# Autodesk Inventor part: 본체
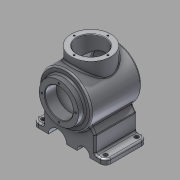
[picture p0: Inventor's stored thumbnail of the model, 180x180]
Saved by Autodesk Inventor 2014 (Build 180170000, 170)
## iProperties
Created: 2018-08
Part Number: 본체
Material: Aluminum 6061
Document SubType Name: Modeling
Designer: user
Density: 2.71 g/cm^3
Appearance: Aluminum - Flat
Mass: 1862.39 g
Surface Area: 1087.4 cm^2
Volume: 687.23 cm^3
Author: user
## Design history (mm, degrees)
sketch "Sketch1"
  geometry: L1 (0, 0)-(206.357, 0); L2 (0, 0)-(0, 38); L3 (0, 38)-(12, 38); L4 (12, 38)-(12, 50); L5 (12, 50)-(108.671, 50); L6 (120, 116)-(120, 0); L7 (0, 0)-(120, 0); A1 r 116 centre (4, 0) between (120, 0) and (108.671, 50)
  constraints: 14 end point, 3 perpendicular, 2 parallel, 2 point on circle, 1 centre point, 1 horizontal, 1 tangent
  dimensions: "d0" = 76 diameter of L3 L1; "d1" = 100 diameter of L5 L1; "d2" = 12 distance between parallel lines of L2 L4; "d3" = 232 diameter of A1; "d5" = 0 vertical distance of L1.start A1.centre; "d6" = 108 distance between parallel lines of L4 L6
revolve "Revolution1" sketch "Sketch1" stored, may be unused: angle "d7" = 90 deg
sketch "Sketch2"
  geometry: L1 (0, 0)-(931.016, 0); L2 (0, 0)-(0, 27); L3 (0, 27)-(22, 27); L4 (22, 27)-(22, 40); L5 (22, 40)-(102.163, 40); L6 (110, 0)-(0, 0); A1 r 116 centre (4, 0) between (108.671, -50) and (108.671, 50) reference; A2 r 106 centre (4, 0) between (110, 0) and (102.163, 40)
  constraints: 12 end point, 3 parallel, 2 perpendicular, 2 point on circle, 1 centre point, 1 horizontal, 1 point on line
  dimensions: "d9" = 54 diameter of L3 L1; "d10" = 80 diameter of L5 L1; "d11" = 22 distance from line of L4.end L2; "d13" = 10 radial gap between concentric circles of A1 A2
revolve "Revolution2" sketch "Sketch2" stored, may be unused: angle "d14" = 90 deg
chamfer "Chamfer1" distance "d15" = 1; stored, may be unused: second distance "d16" = 2, angle "d17" = 45 deg
workplane "Work Plane1"
sketch "Sketch3"
  geometry: L1 (0, 0)-(0, -150.146); L2 (0, -82)-(70, -82); L3 (70, -82)-(70, -72); L4 (70, -72)-(50, -72); L5 (50, -72)-(50, -40); L6 (50, -40)-(41.509, -27.874); L7 (0, -82)-(0, -50); A1 r 50 centre (0, 0) between (0, -50) and (41.509, -27.874); 1 further point
  constraints: 14 end point, 2 parallel, 2 perpendicular, 2 point on circle, 1 centre point, 1 coincident, 1 collinear, 1 point on line, 1 vertical, 2 other
  dimensions: "d19" = 20 distance between parallel lines of L5 L3; "d20" = 82 distance from line of L2 L1.start; "d21" = 10 distance between parallel lines of L2 L4; "d22" = 35 deg angle of L6 L3; "d23" = 70 distance between parallel lines of L1 L3; "d93" = 40 vertical distance of L5.end L1.start
extrude "Extrusion1" join sketch "Sketch3" distance "d24" = 80; taper "d25" = 0 deg
sketch "Sketch4"
  geometry: L1 (20, 0)-(0, 0) reference; L2 (20, 0)-(20, 80) reference; L3 (0, 80)-(20, 80) reference; C1 r 4 at (10, 70); C2 r 4 at (10, 10); 1 further point
  constraints: 2 centre point
  dimensions: "d26" = 10 distance from line of L2 C1.centre; "d27" = 10 distance from line of C1.centre L3; "d28" = 8 diameter of C1; "d29" = 8 diameter of C2; "d30" = 0 horizontal distance of C1.centre C2.centre; "d31" = 10 distance from line of L1 C2.centre
extrude "Extrusion2" cut sketch "Sketch4" distance "d32" = 80; taper "d33" = 0 deg
fillet "Fillet1" dims "d34" = 10
fillet "Fillet2" dims "d35" = 3
fillet "Fillet3" dims "d36" = 3
mirror "Mirror1"
fillet "Fillet4" dims "d37" = 3
sketch "Sketch5"
  geometry: L1 (-60, -82)-(60, -82) reference; C1 r 12.5 at (27.5, -82); C2 r 17.5 at (-22.5, -82); A1 r 53 centre (0, 0) between (-41.453, -33.024) and (41.453, -33.024) reference
  constraints: 2 centre point
  dimensions: "d38" = 35 diameter of C2; "d39" = 12.5 radius of C1; "d40" = 0 distance from line of L1 C2.centre; "d41" = 0 distance from line of L1 C1.centre; "d42" = 22.5 horizontal distance of C2.centre A1.centre; "d43" = 27.5 horizontal distance of A1.centre C1.centre
extrude "Extrusion3" cut sketch "Sketch5" distance "d44" = 80; taper "d45" = 0 deg
workplane "Work Plane2"
sketch "Sketch6"
  geometry: L1 (120, -18)-(20, -18) reference; C1 r 38 at (70, 32); 1 further point
  constraints: 1 centre point
  dimensions: "d47" = 76 diameter of C1; "d48" = 0 horizontal distance of C1.centre point (70, -30); "d49" = 50 distance from line of C1.centre L1
extrude "Extrusion4" join sketch "Sketch6" stored distance "d50" = 80; taper "d51" = 0 deg
sketch "Sketch7"
  geometry: C1 r 38 at (0, 0) reference; C2 r 27 at (0, 0); 1 further point
  constraints: 1 centre point, 1 coincident
  dimensions: "d52" = 54 diameter of C2
extrude "Extrusion5" cut sketch "Sketch7" distance "d53" = 62.25; taper "d54" = 0 deg
sketch "Sketch8" dims "d55" = 65
  geometry: L1 (0, 0)-(0, 32.5); C1 r 38 at (0, 0) reference; 2 further points
  constraints: 2 coincident, 2 end point, 1 vertical, 1 vertical alignment, 2 other
hole "Hole1" sketch "Sketch8" at (0, 32.5) diameter "d56" = 3.242; stored, may be unused: countersink angle "d60" = 90 deg, drill point angle "d62" = 118 deg; dims "d57" = 8, "d58" = 4, "d59" = 2, "d61" = 10
pattern_circular "Circular Pattern1" dims angle "d64" = 360 deg
sketch "Sketch9" dims "d66" = 65
  geometry: L1 (0, 0)-(0, 32.5); C1 r 28 at (0, 0) reference; 1 further point
  constraints: 2 coincident, 2 end point, 1 vertical, 1 vertical alignment, 2 other
hole "Hole2" sketch "Sketch9" at (0, 32.5) diameter "d67" = 3.242; stored, may be unused: countersink angle "d71" = 90 deg, drill point angle "d73" = 118 deg; dims "d68" = 8, "d69" = 4, "d70" = 2, "d72" = 10
pattern_circular "Circular Pattern2" dims angle "d75" = 360 deg
chamfer "Chamfer2" distance "d77" = 1; stored, may be unused: second distance "d78" = 2, angle "d79" = 45 deg
fillet "Fillet5" dims "d80" = 3
fillet "Fillet6" dims "d81" = 3
workplane "Work Plane3"
sketch "Sketch11"
  geometry: C1 r 32.5 at (0, 0); 1 further point
  constraints: 1 centre point, 1 coincident, 1 other
  dimensions: "d89" = 65 diameter of C1
emboss "Emboss2" sketch "Sketch11" dims "d0" = 76, "d1" = 100, "d2" = 12, "d3" = 232, "d5" = 0, "d6" = 108, "d90" = 0.5, "d91" = 0
body "Solid1"
other parameters: "d18" = -8, "d46" = -147, "d82" = 148
